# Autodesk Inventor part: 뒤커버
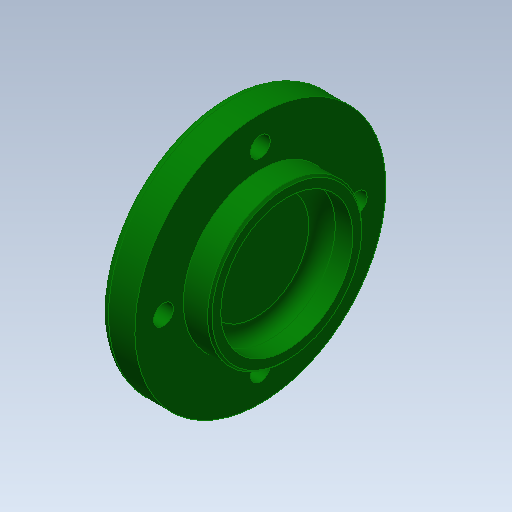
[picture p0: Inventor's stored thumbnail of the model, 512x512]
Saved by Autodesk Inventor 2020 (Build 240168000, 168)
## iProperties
Created: 2015-12
Part Number: 뒤커버
Material: 알루미늄 6061
Document SubType Name: Modeling
Designer: mduedu
Density: 2.71 g/cm^3
Appearance: 진녹색
Author: mduedu
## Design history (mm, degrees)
sketch "스케치1"
  geometry: L1 (0, 0)-(14, 0); L2 (14, 0)-(14, 17.5); L3 (14, 17.5)-(8, 17.5); L4 (8, 17.5)-(8, 28.5); L5 (8, 28.5)-(0, 28.5); L6 (0, 28.5)-(0, 0)
  constraints: 12 end point, 4 parallel, 1 horizontal, 1 perpendicular
  dimensions: "d0" = 14 distance between parallel lines of L2 L6; "d2" = 8 distance of L4.end L5.end; "d3" = 57 diameter of L5 L1; "d4" = 35 diameter of L3 L1
revolve "회전1" sketch "스케치1" stored, may be unused: angle "d5" = 90 deg
hole "구멍1" diameter "d8" = 30; stored, may be unused: countersink angle "d12" = 90 deg, drill point angle "d14" = 0 deg; dims "d9" = 6, "d10" = 4, "d11" = 2, "d13" = 7, "d39" = 10, "d40" = 10
fillet "모깎기3" dims "d38" = 2
fillet "모깎기4" dims "d41" = 3
chamfer "모따기2" distance "d42" = 0.5; stored, may be unused: second distance "d43" = 2, angle "d44" = 45 deg
sketch "스케치2" dims "d45" = 42
  geometry: 6 further points
  constraints: 2 vertical alignment, 1 coincident, 7 other
  dimensions: "d48" = 360 deg dimension on point (0, 0) point (0, 21) (derived)
sketch "스케치3" dims "d57" = 44
  geometry: C1 r 26.5 at (0, 0) reference; 5 further points
  constraints: 1 coincident, 1 horizontal alignment, 2 other
hole "구멍4" sketch "스케치3" at (-22, 0), (0, -22), (22, 0), (0, 22) diameter "d50" = 4.5; stored, may be unused: countersink angle "d54" = 90 deg, drill point angle "d56" = 0 deg; dims "d51" = 6, "d52" = 8, "d53" = 4.6, "d55" = 8
node "솔리드1"
